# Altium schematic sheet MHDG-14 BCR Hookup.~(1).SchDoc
size B
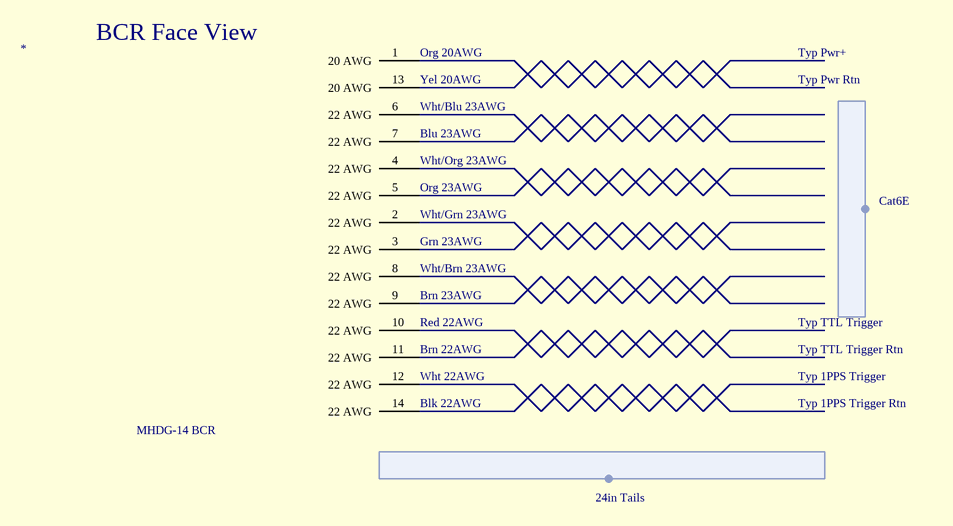
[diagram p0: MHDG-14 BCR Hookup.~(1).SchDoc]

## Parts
*  MHDG-14 BCR

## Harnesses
Cat6E: 
24in Tails: 

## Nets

Not connected (* = marked no-connect by the designer): * 1(20_AWG) 2(22_AWG) 3(22_AWG) 4(22_AWG) 5(22_AWG) 6(22_AWG) 7(22_AWG) 8(22_AWG) 9(22_AWG) 10(22_AWG) 11(22_AWG) 12(22_AWG) 13(20_AWG) 14(22_AWG)

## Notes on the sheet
- BCR Face View
- (near *) Org 20AWG
- Typ Pwr+
- (near *) Yel 20AWG
- (near *) Wht/Blu 23AWG
- (near *) Blu 23AWG
- Typ Pwr Rtn
- (near *) Wht/Org 23AWG
- (near *) Org 23AWG
- (near *) Wht/Grn 23AWG
- (near *) Grn 23AWG
- (near *) Wht/Brn 23AWG
- (near *) Brn 23AWG
- (near *) Red 22AWG
- Typ TTL Trigger
- (near *) Brn 22AWG
- (near *) Wht 22AWG
- (near *) Blk 22AWG
- Typ TTL Trigger Rtn
- Typ 1PPS Trigger
- Typ 1PPS Trigger Rtn

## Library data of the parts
* = MHDG-14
